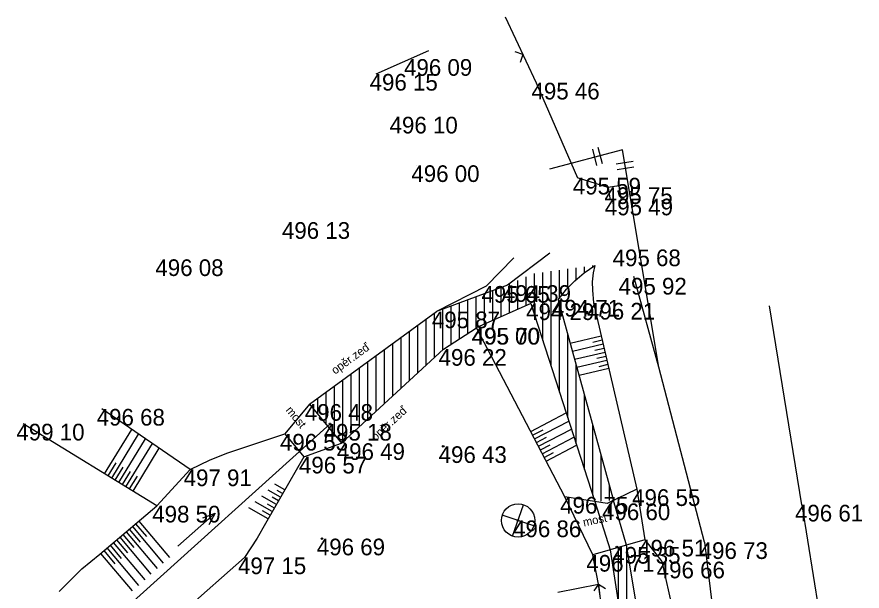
# Model space of a CAD drawing. Extents: x -554123 to -553118, y -1076825 to -1073672.
# Drawn here: x -553487.5 to -553436.8, y -1076726.2 to -1076691.7 of the extents above; entities that cross this region are included whole.
import ezdxf

# ---------------------------------------------------------------- set-up
doc = ezdxf.new("R2010")
doc.units = 0
for name, color, linetype in [('1', 7, 'Continuous'), ('12', 7, 'Continuous'), ('14', 7, 'Continuous'), ('17', 7, 'Continuous'), ('18', 7, 'Continuous'), ('26', 7, 'Continuous'), ('27', 7, 'Continuous'), ('28', 7, 'Continuous'), ('32', 7, 'Continuous'), ('34', 7, 'Continuous'), ('52', 7, 'Continuous'), ('6', 7, 'Continuous'), ('62', 7, 'Continuous')]:
    doc.layers.add(name, color=color, linetype=linetype)

# ---------------------------------------------------------------- blocks, each defined once
blk = doc.blocks.new('POINT_DISPLAY')
blk.add_line((0, 0), (0, 0))
blk = doc.blocks.new('T')
at = {"layer": '6'}
blk.add_circle((0, 0), 0.05, dxfattribs=at)
blk = doc.blocks.new('STJ')
at = {"layer": '34'}
for p, q in [((-0.327, -0.945), (0.327, 0.945)), ((0.945, -0.327), (-0.945, 0.327))]:
    blk.add_line(p, q, dxfattribs=at)
for radius in [1, 0.0496]:
    blk.add_circle((0, 0), radius, dxfattribs=at)
blk = doc.blocks.new('VOTOK')
at = {"layer": '28'}
for p, q in [((-3.001, 0), (0, 0)), ((-0.75, 0.282), (0, 0)), ((0, 0), (-0.75, -0.28))]:
    blk.add_line(p, q, dxfattribs=at)
blk = doc.blocks.new('ROV')
at = {"layer": '62'}
for p, q in [((-0.348, -0.51), (-0.348, 0.51)), ((0, -0.51), (0, 0.51))]:
    blk.add_line(p, q, dxfattribs=at)

msp = doc.modelspace()

# ---------------------------------------------------------------- linework, layer by layer
at = {"layer": '12'}
for p, q in [((-553458.18, -1076691.74), (-553456.33, -1076695.69)), ((-553457.12, -1076694.004), (-553457.59, -1076693.834)), ((-553457.12, -1076694.004), (-553457.29, -1076694.475)), ((-553456.33, -1076695.69), (-553453.84, -1076701.39)), ((-553455.03, -1076726.24), (-553452.578, -1076725.751)), ((-553452.578, -1076725.751), (-553452.856, -1076726.167)), ((-553452.578, -1076725.751), (-553452.162, -1076726.029)), ((-553452.578, -1076725.751), (-553450.54, -1076744.62))]:
    msp.add_line(p, q, dxfattribs=at)
at = {"layer": '14'}
msp.add_line((-553465.92, -1076695.16), (-553462.755, -1076693.757), dxfattribs=at)
at = {"layer": '17'}
for p, q in [((-553452.01, -1076701.97), (-553453.84, -1076701.39)), ((-553448.97, -1076712.74), (-553450.47, -1076707.31)), ((-553440.39, -1076721), (-553442.33, -1076709.06)), ((-553446.23, -1076723.25), (-553448.97, -1076712.74)), ((-553440.39, -1076721), (-553438.01, -1076735.73)), ((-553446.23, -1076723.25), (-553443.91, -1076741.76))]:
    msp.add_line(p, q, dxfattribs=at)
at = {"layer": '18'}
for p, q in [((-553451.361, -1076701.867), (-553452.01, -1076701.97)), ((-553452.01, -1076701.97), (-553451.89, -1076702.73)), ((-553451.361, -1076701.867), (-553451.24, -1076702.63)), ((-553469.93, -1076714.96), (-553462.31, -1076709.41)), ((-553461.89, -1076711.66), (-553459.9, -1076710.39)), ((-553468, -1076717.31), (-553461.89, -1076711.66)), ((-553469.93, -1076714.96), (-553471.41, -1076716.75)), ((-553469.93, -1076714.96), (-553468, -1076717.31)), ((-553471.41, -1076716.75), (-553470.27, -1076718.12)), ((-553470.27, -1076718.12), (-553468, -1076717.31)), ((-553450.28, -1076720.07), (-553452.07, -1076720.92)), ((-553450.28, -1076720.07), (-553449.81, -1076723.1)), ((-553452.07, -1076720.92), (-553454.6, -1076720.53)), ((-553452.92, -1076724.01), (-553454.6, -1076720.53)), ((-553449.81, -1076723.1), (-553452.92, -1076724.01))]:
    msp.add_line(p, q, dxfattribs=at)
at = {"layer": '26'}
for p, q in [((-553452.416, -1076710.887), (-553454.286, -1076711.322)), ((-553452.359, -1076711.13), (-553452.917, -1076711.26)), ((-553452.302, -1076711.374), (-553454.153, -1076711.804)), ((-553452.246, -1076711.617), (-553452.798, -1076711.746)), ((-553452.189, -1076711.861), (-553454.019, -1076712.287)), ((-553452.132, -1076712.104), (-553452.678, -1076712.231)), ((-553452.076, -1076712.348), (-553453.885, -1076712.769)), ((-553452.019, -1076712.591), (-553452.559, -1076712.717)), ((-553451.963, -1076712.835), (-553453.752, -1076713.251)), ((-553456.651, -1076716.605), (-553454.525, -1076715.494)), ((-553456.42, -1076717.049), (-553454.369, -1076715.977)), ((-553482.216, -1076719.139), (-553480.588, -1076716.482)), ((-553481.789, -1076719.4), (-553480.174, -1076716.765)), ((-553456.535, -1076716.827), (-553455.909, -1076716.5)), ((-553456.188, -1076717.492), (-553454.213, -1076716.46)), ((-553481.363, -1076719.661), (-553479.761, -1076717.047)), ((-553456.304, -1076717.27), (-553455.7, -1076716.954)), ((-553455.956, -1076717.935), (-553454.057, -1076716.942)), ((-553480.937, -1076719.922), (-553479.348, -1076717.329)), ((-553480.51, -1076720.184), (-553478.934, -1076717.612)), ((-553456.072, -1076717.713), (-553455.491, -1076717.41)), ((-553455.725, -1076718.378), (-553453.901, -1076717.425)), ((-553455.841, -1076718.156), (-553455.282, -1076717.864)), ((-553482.003, -1076719.269), (-553481.516, -1076718.475)), ((-553481.576, -1076719.531), (-553481.094, -1076718.743)), ((-553481.15, -1076719.792), (-553480.671, -1076719.011)), ((-553480.724, -1076720.053), (-553480.249, -1076719.278)), ((-553471.41, -1076720.111), (-553472.002, -1076719.772)), ((-553471.658, -1076720.544), (-553472.392, -1076720.124)), ((-553471.534, -1076720.327), (-553471.863, -1076720.139)), ((-553472.155, -1076721.412), (-553473.174, -1076720.828)), ((-553471.907, -1076720.978), (-553472.783, -1076720.476)), ((-553471.783, -1076720.761), (-553472.154, -1076720.549)), ((-553472.404, -1076721.846), (-553473.566, -1076721.181)), ((-553472.031, -1076721.195), (-553472.445, -1076720.958)), ((-553472.28, -1076721.629), (-553472.737, -1076721.367)), ((-553480.547, -1076722.299), (-553478.694, -1076724.492)), ((-553480.356, -1076722.138), (-553479.705, -1076722.908)), ((-553480.165, -1076721.977), (-553478.323, -1076724.157)), ((-553481.119, -1076722.783), (-553480.462, -1076723.561)), ((-553480.929, -1076722.622), (-553479.066, -1076724.827)), ((-553480.738, -1076722.461), (-553480.084, -1076723.235)), ((-553481.692, -1076723.267), (-553479.809, -1076725.496)), ((-553481.501, -1076723.106), (-553480.841, -1076723.887)), ((-553481.31, -1076722.945), (-553479.437, -1076725.161)), ((-553482.265, -1076723.751), (-553481.599, -1076724.54)), ((-553482.074, -1076723.59), (-553480.18, -1076725.831)), ((-553481.883, -1076723.429), (-553481.22, -1076724.214)), ((-553482.456, -1076723.913), (-553480.552, -1076726.166))]:
    msp.add_line(p, q, dxfattribs=at)
at = {"layer": '27'}
for p, q in [((-553457.672, -1076706.196), (-553459.32, -1076707.88)), ((-553459.32, -1076707.88), (-553462.31, -1076709.41)), ((-553452.88, -1076708.89), (-553450.28, -1076720.07)), ((-553454.6, -1076720.53), (-553459.9, -1076710.39)), ((-553477.08, -1076718.88), (-553482.39, -1076715.25)), ((-553479.08, -1076721.06), (-553487.11, -1076716.14)), ((-553479.08, -1076721.06), (-553477.08, -1076718.88)), ((-553449.81, -1076723.1), (-553448.78, -1076724.41)), ((-553478.17, -1076728), (-553473.83, -1076724.16)), ((-553452.578, -1076725.751), (-553452.92, -1076724.01)), ((-553448.78, -1076724.41), (-553445.77, -1076737.77)), ((-553450.19, -1076742.9), (-553452.578, -1076725.751))]:
    msp.add_line(p, q, dxfattribs=at)
for points in [[(-553452.81, -1076706.64), (-553452.897, -1076707.091), (-553452.955, -1076707.626), (-553452.952, -1076708.128), (-553452.88, -1076708.89)], [(-553477.08, -1076718.88), (-553475.888, -1076718.307), (-553474.831, -1076717.887), (-553471.41, -1076716.75)], [(-553470.27, -1076718.12), (-553472.558, -1076722.115), (-553473.065, -1076722.998), (-553473.83, -1076724.16)], [(-553484.94, -1076726.2), (-553483.576, -1076724.851), (-553482.505, -1076723.954), (-553479.08, -1076721.06)]]:
    msp.add_lwpolyline(points, dxfattribs=at)
at = {"layer": '28'}
for p, q in [((-553455.51, -1076705.9), (-553458.05, -1076707.83)), ((-553458.05, -1076707.83), (-553462.31, -1076709.41)), ((-553456.65, -1076708.92), (-553459.92, -1076710.39)), ((-553456.65, -1076708.92), (-553452.808, -1076720.806)), ((-553455.01, -1076708.71), (-553451.678, -1076720.734)), ((-553481.106, -1076727.336), (-553468.69, -1076716.15)), ((-553452.808, -1076720.806), (-553451.877, -1076723.705)), ((-553450.902, -1076723.42), (-553451.678, -1076720.734)), ((-553451.877, -1076723.705), (-553449.03, -1076742.64)), ((-553447.73, -1076742.11), (-553450.902, -1076723.42))]:
    msp.add_line(p, q, dxfattribs=at)
msp.add_lwpolyline([(-553455.01, -1076708.71), (-553454.505, -1076708.059), (-553454.004, -1076707.573), (-553453.444, -1076707.086), (-553452.81, -1076706.64)], dxfattribs=at)
at = {"layer": '32'}
for p, q in [((-553456.43, -1076709.601), (-553456.43, -1076707.127)), ((-553455.93, -1076711.147), (-553455.93, -1076707.06)), ((-553455.43, -1076712.694), (-553455.43, -1076706.993)), ((-553454.93, -1076708.607), (-553454.93, -1076706.925)), ((-553454.43, -1076707.986), (-553454.43, -1076706.858)), ((-553453.93, -1076707.509), (-553453.93, -1076706.791)), ((-553453.43, -1076707.076), (-553453.43, -1076706.723)), ((-553452.93, -1076706.724), (-553452.93, -1076706.656)), ((-553457.43, -1076709.271), (-553457.43, -1076707.555)), ((-553456.93, -1076709.046), (-553456.93, -1076707.333)), ((-553458.93, -1076709.945), (-553458.93, -1076708.156)), ((-553458.43, -1076709.72), (-553458.43, -1076707.971)), ((-553457.93, -1076709.495), (-553457.93, -1076707.777)), ((-553459.93, -1076710.396), (-553459.93, -1076708.527)), ((-553459.43, -1076710.17), (-553459.43, -1076708.342)), ((-553461.43, -1076711.363), (-553461.43, -1076709.084)), ((-553460.93, -1076711.041), (-553460.93, -1076708.898)), ((-553460.43, -1076710.719), (-553460.43, -1076708.713)), ((-553454.93, -1076714.241), (-553454.93, -1076708.999)), ((-553462.43, -1076712.159), (-553462.43, -1076709.497)), ((-553461.93, -1076711.697), (-553461.93, -1076709.269)), ((-553462.93, -1076712.622), (-553462.93, -1076709.862)), ((-553463.93, -1076713.546), (-553463.93, -1076710.59)), ((-553463.43, -1076713.084), (-553463.43, -1076710.226)), ((-553464.43, -1076714.009), (-553464.43, -1076710.954)), ((-553454.43, -1076715.788), (-553454.43, -1076710.803)), ((-553465.43, -1076714.933), (-553465.43, -1076711.682)), ((-553464.93, -1076714.471), (-553464.93, -1076711.318)), ((-553465.93, -1076715.396), (-553465.93, -1076712.047)), ((-553466.43, -1076715.858), (-553466.43, -1076712.411)), ((-553453.93, -1076717.335), (-553453.93, -1076712.607)), ((-553467.43, -1076716.783), (-553467.43, -1076713.139)), ((-553466.93, -1076716.321), (-553466.93, -1076712.775)), ((-553467.93, -1076717.245), (-553467.93, -1076713.503)), ((-553468.93, -1076716.178), (-553468.93, -1076714.232)), ((-553468.43, -1076716.786), (-553468.43, -1076713.867)), ((-553469.43, -1076715.569), (-553469.43, -1076714.596)), ((-553453.43, -1076718.882), (-553453.43, -1076714.412)), ((-553452.93, -1076720.429), (-553452.93, -1076716.216)), ((-553452.43, -1076720.782), (-553452.43, -1076718.02)), ((-553451.93, -1076720.75), (-553451.93, -1076719.825)), ((-553451.377, -1076727.03), (-553451.377, -1076723.559)), ((-553450.877, -1076730.356), (-553450.877, -1076723.567))]:
    msp.add_line(p, q, dxfattribs=at)
at = {"layer": '62'}
for p, q in [((-553451.14, -1076699.72), (-553455.53, -1076700.87)), ((-553448.97, -1076712.74), (-553451.14, -1076699.72))]:
    msp.add_line(p, q, dxfattribs=at)

# ---------------------------------------------------------------- block references
at = {"layer": '1'}
for p in [(-553463.95, -1076694.27), (-553465.92, -1076695.16), (-553456.33, -1076695.69), (-553464.72, -1076697.73), (-553463.52, -1076700.64), (-553453.84, -1076701.39), (-553451.95, -1076701.96), (-553451.93, -1076702.64), (-553471.18, -1076704.05), (-553478.88, -1076706.28), (-553451.09, -1076707.39), (-553459.32, -1076707.88), (-553458.05, -1076707.83), (-553456.65, -1076708.92), (-553455.01, -1076708.71), (-553452.88, -1076708.89), (-553462.31, -1076709.41), (-553459.92, -1076710.39), (-553459.9, -1076710.39), (-553461.89, -1076711.66), (-553482.39, -1076715.25), (-553469.93, -1076714.96), (-553487.11, -1076716.14), (-553468.69, -1076716.15), (-553471.41, -1076716.75), (-553468, -1076717.31), (-553461.9, -1076717.49), (-553470.27, -1076718.12), (-553477.08, -1076718.88), (-553450.28, -1076720.07), (-553454.6, -1076720.53), (-553479.08, -1076721.06), (-553452.07, -1076720.92), (-553440.39, -1076721), (-553457.41, -1076721.94), (-553469.17, -1076723.03), (-553449.81, -1076723.1), (-553446.23, -1076723.25), (-553451.48, -1076723.53), (-553473.83, -1076724.16), (-553452.92, -1076724.01), (-553448.78, -1076724.41)]:
    msp.add_blockref('POINT_DISPLAY', p, dxfattribs=at)
at = {"layer": '28', "xscale": 1.0000004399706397, "yscale": 1.0000004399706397, "rotation": 41.333356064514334}
msp.add_blockref('VOTOK', (-553475.578, -1076721.503), dxfattribs=at)
at = {"layer": '32'}
msp.add_blockref('POINT_DISPLAY', (-553465.92, -1076695.16), dxfattribs=at)
at = {"layer": '34'}
msp.add_blockref('STJ', (-553457.41, -1076721.94), dxfattribs=at)
at = {"layer": '6'}
for p in [(-553468.69, -1076716.15), (-553461.9, -1076717.49), (-553469.17, -1076723.03), (-553451.48, -1076723.53)]:
    msp.add_blockref('T', p, dxfattribs=at)
at = {"layer": '62'}
for p, xscale, yscale, rotation in [((-553452.468, -1076700.068), 0.9999978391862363, 0.9999978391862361, 14.67934285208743), ((-553450.958, -1076700.811), 0.9999991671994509, 0.9999991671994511, -80.53776551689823)]:
    msp.add_blockref('ROV', p, dxfattribs=dict(at, xscale=xscale, yscale=yscale, rotation=rotation))

# ---------------------------------------------------------------- texts
at = {"layer": '52'}
for s, rotation, p in [('opěr.zeď', 36.0676, (-553468.387, -1076713.204)), ('most', 309.3955, (-553471.378, -1076715.338)), ('opěr.zeď', 42.76, (-553465.956, -1076717.195)), ('most', 11.6964, (-553453.462, -1076722.303))]:
    msp.add_text(s, height=0.5, rotation=rotation, dxfattribs=at).set_placement(p)
at = {"layer": '6'}
for s, p in [('496 09 ', (-553464.25, -1076695.27)), ('496 15 ', (-553466.315, -1076696.16)), ('495 46 ', (-553456.604, -1076696.69)), ('496 10 ', (-553465.117, -1076698.73)), ('496 00 ', (-553463.81, -1076701.64)), ('495 59 ', (-553454.126, -1076702.39)), ('495 75 ', (-553452.222, -1076702.96)), ('495 49 ', (-553452.204, -1076703.64)), ('496 13 ', (-553471.575, -1076705.05)), ('495 68 ', (-553451.736, -1076706.69)), ('496 08 ', (-553479.168, -1076707.28)), ('495 92 ', (-553451.376, -1076708.39)), ('495 65 ', (-553459.606, -1076708.88)), ('494 39 ', (-553458.324, -1076708.83)), ('494 29 ', (-553456.924, -1076709.92)), ('494 71 ', (-553455.377, -1076709.71)), ('496 21 ', (-553453.273, -1076709.89)), ('495 87 ', (-553462.582, -1076710.41)), ('495 00 ', (-553460.198, -1076711.39)), ('495 70 ', (-553460.174, -1076711.39)), ('496 22 ', (-553462.176, -1076712.66)), ('496 68 ', (-553482.688, -1076716.25)), ('496 48 ', (-553470.204, -1076715.96)), ('499 10 ', (-553487.507, -1076717.14)), ('495 18 ', (-553469.073, -1076717.15)), ('496 53 ', (-553471.696, -1076717.75)), ('496 49 ', (-553468.286, -1076718.31)), ('496 43 ', (-553462.174, -1076718.49)), ('496 57 ', (-553470.554, -1076719.12)), ('497 91 ', (-553477.471, -1076719.88)), ('496 55 ', (-553450.566, -1076721.07)), ('496 75 ', (-553454.884, -1076721.53)), ('498 50 ', (-553479.356, -1076722.06)), ('496 60 ', (-553452.37, -1076721.92)), ('496 61 ', (-553440.795, -1076722)), ('496 86 ', (-553457.708, -1076722.94)), ('496 69 ', (-553469.48, -1076724.03)), ('496 51 ', (-553450.203, -1076724.1)), ('496 73 ', (-553446.514, -1076724.25)), ('495 35 ', (-553451.754, -1076724.53)), ('497 15 ', (-553474.211, -1076725.16)), ('496 71 ', (-553453.311, -1076725.01)), ('496 66 ', (-553449.09, -1076725.41))]:
    msp.add_text(s, height=1, dxfattribs=at).set_placement(p)

doc.saveas('drawing.dxf')
